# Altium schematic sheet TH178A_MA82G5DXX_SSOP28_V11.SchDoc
size 274 x 190 mm; PageSetup: Record=PageOptions|CenterHorizontal=True|CenterVertical=True|PrintScale=1.53|XCorrection=1.00|YCorrection=1.00|PrintKind=0|BorderSize=5000000|LeftOffset=0|BottomOffset=0|Orientation=2|PaperLength=1000|PaperWidth=1000|Scale=100|PaperSource=7|PrintQuality=-4|MediaType=1|DitherType=10|PaperKind=12" x 18"|PrintScaleMode=1
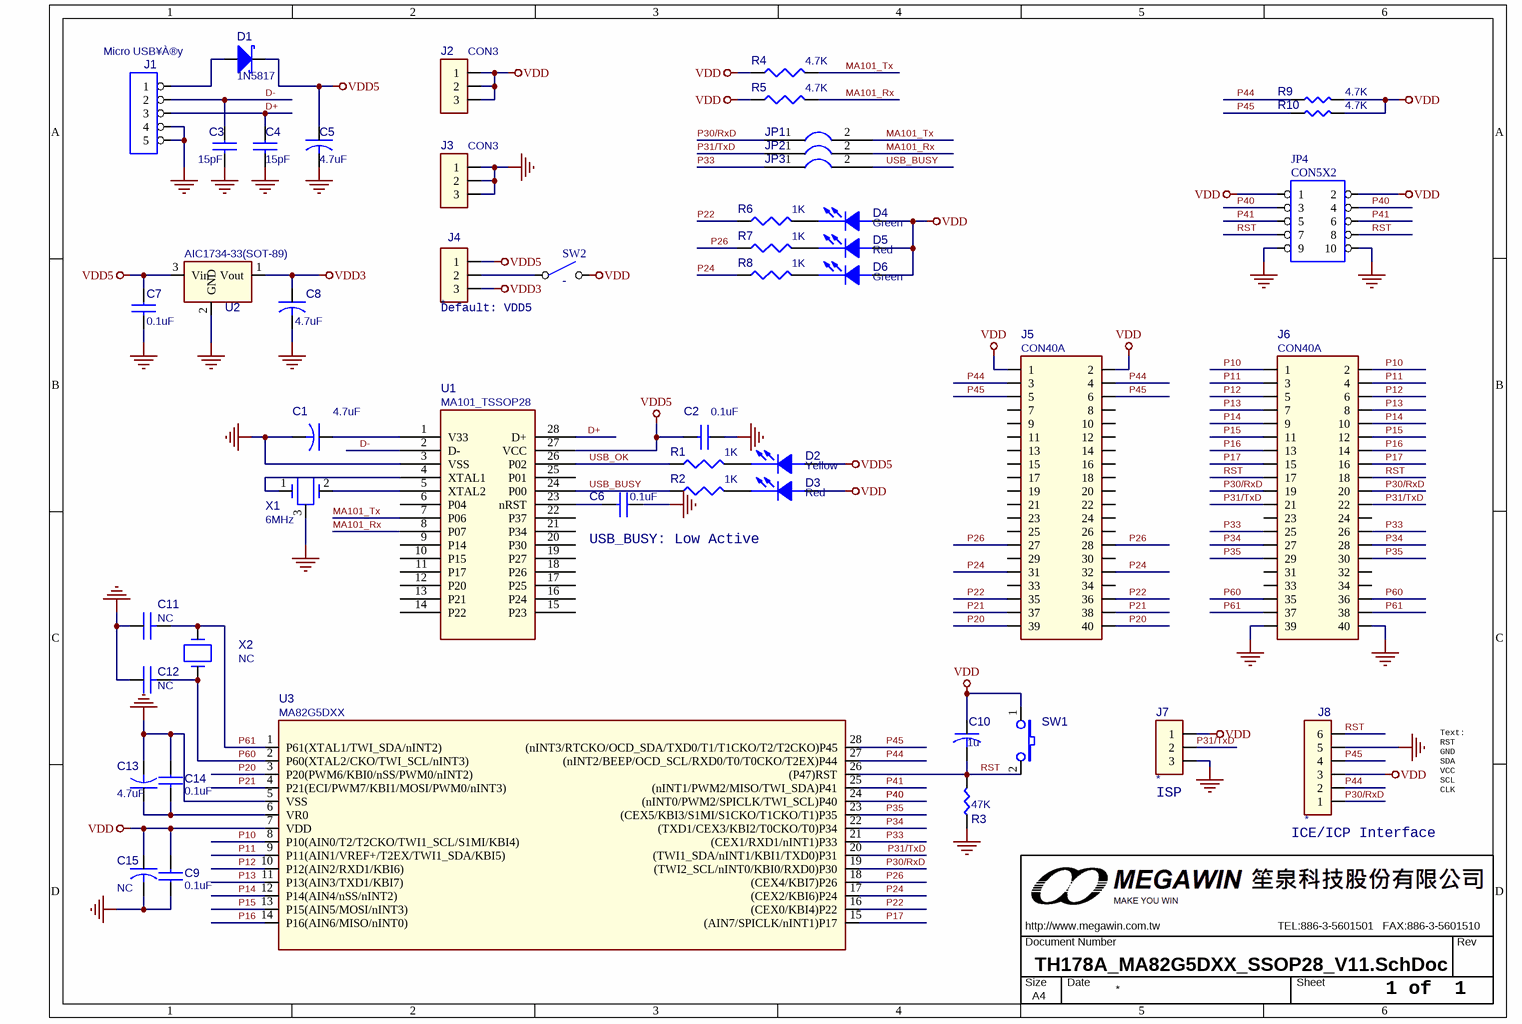
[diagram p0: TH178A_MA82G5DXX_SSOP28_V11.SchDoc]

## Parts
C1  4.7uF  [0805C]
C2  0.1uF  [0805C]
C3  15pF  [0805C]
C4  15pF  [0805C]
C5  4.7uF  [1206C]
C6  0.1uF  [0805C]
C7  0.1uF  [0805C]
C8  4.7uF  [0805C]
C9  0.1uF  [0805C]
C10  1u  [0805C]
C11  NC  [0805C]
C12  NC  [0805C]
C13  4.7uF  [0805C]
C14  0.1uF  [0805C]
C15  NC  [0805C]
D1  1N5817  [D5817_SMD_1]
D2  Yellow  [0805D]
D3  Red  [0805D]
D4  Green  [0805D]
D5  Red  [0805D]
D6  Green  [0805D]
J1  Micro USB¥À®y  [JACK_USB_SMD290X220P065]
J2  CON3  [PS3P254]
J3  CON3  [PS3P254]
J4  *  [JUMP3_SMD]
J5  CON40A  [PS20X2P254]
J6  CON40A  [PS20X2P254]
J7  *  [PS3P254f_90]
J8  *  [PS6P254F_90]
JP1  JUMPER2  [PS2P254]  (value not drawn)
JP2  JUMPER2  [PS2P254]  (value not drawn)
JP3  JUMPER2  [PS2P254]  (value not drawn)
JP4  CON5X2  [PS5X2P254]
MW1  OrgAddr3: TEL:886-3-5601501   FAX:886-3-5601510  Page Size: A4  [MEGAWIN10_1]  (hidden comment: MW_A4_1)  (graphical)
R1  1K  [0805R]
R2  1K  [0805R]
R3  47K  [0805R]
R4  4.7K  [0805R]
R5  4.7K  [0805R]
R6  1K  [0805R]
R7  1K  [0805R]
R8  1K  [0805R]
R9  4.7K  [0805R]
R10  4.7K  [0805R]
SW1  SW TACT-SPST  [SW_T_2P]  (value not drawn)
SW2  -  [DIP2_SW]
U1  MA101_TSSOP28  [SSOP28_220P065]
U2  AIC1734-33(SOT-89)  [SOT89]
U3  MA82G5DXX  [SSOP28_150P0635]
X1  6MHz  [X3P]
X2  NC  [X49U]

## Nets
GND_POWER: C1.2 C2.1 C3.2 C4.2 C5.2 C6.1 C7.2 C8.2 C9.1 C11.1 C12.1 C13.2 C14.1 C15.2 J1.4 J1.5 J3.1 J3.2 J3.3 J6.39 J6.40 J7.3 J8.5 JP4.9 JP4.10 R3.1 U1.3(VSS) U2.2(GND) U3.5(VSS) X1.3
VDD: C9.2 C10.1(POS) C15.1 D3.1(ANODE) D4.1(ANODE) D5.1(ANODE) D6.1(ANODE) J2.1 J2.2 J2.3 J5.1 J5.2 J7.1 J8.3 JP4.1 JP4.2 R4.1 R5.1 R9.2 R10.2 SW1.1 SW2.2(NO) U3.7(VDD)
VDD3: C8.1 J4.3 U2.1(Vout)
VDD5: C2.2 C5.1 C7.1 D1.2(K) D2.1(ANODE) J4.1 U1.27(VCC) U2.3(Vin)
D+: C4.1 J1.3 U1.28(D+)
D-: C3.1 J1.2 U1.2(D-)
MA101_Rx: JP2.2 R5.2 U1.8(P07)
MA101_Tx: JP1.2 R4.2 U1.7(P06)
P10: J6.1 J6.2 U3.8(P10(AIN0/T2/T2CKO/TWI1_SCL/S1MI/KBI4))
P11: J6.3 J6.4 U3.9(P11(AIN1/VREF+/T2EX/TWI1_SDA/KBI5))
P12: J6.5 J6.6 U3.10(P12(AIN2/RXD1/KBI6))
P13: J6.7 J6.8 U3.11(P13(AIN3/TXD1/KBI7))
P14: J6.9 J6.10 U3.12(P14(AIN4/nSS/nINT2))
P15: J6.11 J6.12 U3.13(P15(AIN5/MOSI/nINT3))
P16: J6.13 J6.14 U3.14(P16(AIN6/MISO/nINT0))
P17: J6.15 J6.16 U3.15((AIN7/SPICLK/nINT1)P17)
P20: J5.39 J5.40 U3.3(P20(PWM6/KBI0/nSS/PWM0/nINT2))
P21: J5.37 J5.38 U3.4(P21(ECI/PWM7/KBI1/MOSI/PWM0/nINT3))
P22: J5.35 J5.36 R6.1 U3.16((CEX0/KBI4)P22)
P24: J5.31 J5.32 R8.1 U3.17((CEX2/KBI6)P24)
P26: J5.27 J5.28 R7.1 U3.18((CEX4/KBI7)P26)
P30/RxD: J6.19 J6.20 J8.1 JP1.1 U3.19((TWI2_SCL/nINT0/KBI0/RXD0)P30)
P31/TxD: J6.21 J6.22 J7.2 JP2.1 U3.20((TWI1_SDA/nINT1/KBI1/TXD0)P31)
P33: J6.25 J6.26 JP3.1 U3.21((CEX1/RXD1/nINT1)P33)
P34: J6.27 J6.28 U3.22((TXD1/CEX3/KBI2/T0CKO/T0)P34)
P35: J6.29 J6.30 U3.23((CEX5/KBI3/S1MI/S1CKO/T1CKO/T1)P35)
P40: JP4.3 JP4.4 U3.24((nINT0/PWM2/SPICLK/TWI_SCL)P40)
P41: JP4.5 JP4.6 U3.25((nINT1/PWM2/MISO/TWI_SDA)P41)
P44: J5.3 J5.4 J8.2 R9.1 U3.27((nINT2/BEEP/OCD_SCL/RXD0/T0/T0CKO/T2EX)P44)
P45: J5.5 J5.6 J8.4 R10.1 U3.28((nINT3/RTCKO/OCD_SDA/TXD0/T1/T1CKO/T2/T2CKO)P45)
P60: C12.2 J6.35 J6.36 U3.2(P60(XTAL2/CKO/TWI_SCL/nINT3)) X2.2
P61: C11.2 J6.37 J6.38 U3.1(P61(XTAL1/TWI_SDA/nINT2)) X2.1
RST: C10.2(NEG) J6.17 J6.18 J8.6 JP4.7 JP4.8 R3.2 SW1.2 U3.26((P47)RST)
USB_BUSY: JP3.2 R2.1 U1.24(P00)
USB_OK: R1.1 U1.26(P02)
NetC1_1: C1.1 U1.1(V33)
NetC6_2: C6.2 U1.23(nRST)
NetC13_1: C13.1 C14.2 U3.6(VR0)
NetD1_1: D1.1(A) J1.1
NetD2_2: D2.2(CATHODE) R1.2
NetD3_2: D3.2(CATHODE) R2.2
NetD4_2: D4.2(CATHODE) R6.2
NetD5_2: D5.2(CATHODE) R7.2
NetD6_2: D6.2(CATHODE) R8.2
NetJ4_2: J4.2 SW2.1(COMMON)
NetU1_4: U1.4(XTAL1) X1.1
NetU1_5: U1.5(XTAL2) X1.2

Not connected (* = marked no-connect by the designer): J5 7 8 9 10 11 12 13 14 15 16 17 18 19 20 21 22 23 24 25 26 29 30 33 34; J6 23 24 31 32 33 34; U1 6(P04) 9(P14) 10(P15) 11(P17) 12(P20) 13(P21) 14(P22) 15(P23) 16(P24) 17(P25) 18(P26) 19(P27) 20(P30) 21(P34) 22(P37) 25(P01)

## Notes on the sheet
- (near J4) Default: VDD5
- USB_BUSY: Low Active
- (near J7) ISP
- (near J8) ICE/ICP Interface
- Text:
  RST
  GND
  SDA
  VCC
  SCL
  CLK
- 1 of  1

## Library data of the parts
C1 C5 C8 C13 C15 = CAP
C2-C4 C6 C7 C9 C14 = CAP NP
C10 = C
C11 C12 = C NP
D1 = DIODE_ZD: Schottky Diode
D2-D6 = LED
J1 = CON5: Connector
J4 J7 = CON3
J8 = CON6
R1 R2 R4-R8 = R_Dup1
R3 R9 R10 = R
SW2 = SW-2
U2 = AIC1734-33(SOT-89)_0
U3 = MG82FG5Dxx_SSOP-28
X1 = CRYSTAL_RC
X2 = CRYSTAL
